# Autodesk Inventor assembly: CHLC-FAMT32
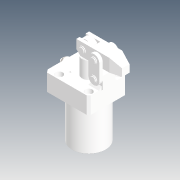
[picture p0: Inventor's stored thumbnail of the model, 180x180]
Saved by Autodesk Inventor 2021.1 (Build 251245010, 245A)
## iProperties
Created: 2019-04
Part Number: CHLC-FAMT32
Description: STEP AP214
Document SubType Name: Assembly
Designer: user
Title: CHLC-FAMT32.STEP
Revision Number: ÈÎºÎ
Sending System: SolidWorks 2016
Preprocessor: SwSTEP 2.0
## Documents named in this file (10)
- D:\Vault_2016\Projekty\Clamptek\Hydraulic\CHLC\CHLC-32\Inventor\CHLC-FAMT32\CHLC-FAMT32.iam
- D:\Vault_2016\Projekty\Clamptek\Hydraulic\CHLC\CHLC-32\Inventor\CHLC-FAMT32\chlc-famT32BT_Ä¬ÈÏ[°´¼Ó¹¤].ipt
- D:\Vault_2016\Projekty\Clamptek\Hydraulic\CHLC\CHLC-32\Inventor\CHLC-FAMT32\CHLC-32-02_1.ipt
- D:\Vault_2016\Projekty\Clamptek\Hydraulic\CHLC\CHLC-32\Inventor\CHLC-FAMT32\CHLC-32-04_1_1.ipt
- D:\Vault_2016\Projekty\Clamptek\Hydraulic\CHLC\CHLC-32\Inventor\CHLC-FAMT32\LHC01D-32-01_1.ipt
- D:\Vault_2016\Projekty\Clamptek\Hydraulic\CHLC\CHLC-32\Inventor\CHLC-FAMT32\CHLC-32-08_1.ipt
- D:\Vault_2016\Projekty\Clamptek\Hydraulic\CHLC\CHLC-32\Inventor\CHLC-FAMT32\CHLC-32-03_1.ipt
- D:\Vault_2016\Projekty\Clamptek\Hydraulic\CHLC\CHLC-32\Inventor\CHLC-FAMT32\socket set screw flat point_iso_ISO 4026 - M5 x 6-S.ipt
- D:\Vault_2016\Projekty\Clamptek\Hydraulic\CHLC\CHLC-32\Inventor\CHLC-FAMT32\Ñ¹±Û.ipt
- D:\Vault_2016\Projekty\Clamptek\Hydraulic\CHLC\CHLC-32\Inventor\CHLC-FAMT32\CZL10µ÷ËÙ·§.ipt
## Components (18 placed, 18 different names)
1. chlc-famT32BT_Ä¬ÈÏ[°´¼Ó¹¤]_1
2. CHLC-32-02_1_2
3. CHLC-32-04_1_1_3
4. LHC01D-32-01_1_4
5. LHC01D-32-01_1_5
6. LHC01D-32-01_1_6
7. LHC01D-32-01_1_7
8. CHLC-32-04_1_1_8
9. LHC01D-32-01_1_9
10. LHC01D-32-01_1_10
11. CHLC-32-08_1_11
12. CHLC-32-03_1_12
13. CHLC-32-03_1_13
14. socket set screw flat point_iso_ISO 4026 - M5 x 6-S_14
15. socket set screw flat point_iso_ISO 4026 - M5 x 6-S_15
16. socket set screw flat point_iso_ISO 4026 - M5 x 6-S_16
17. Ñ¹±Û_17
18. CZL10µ÷ËÙ·§_18
